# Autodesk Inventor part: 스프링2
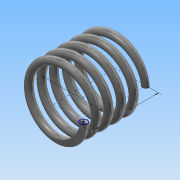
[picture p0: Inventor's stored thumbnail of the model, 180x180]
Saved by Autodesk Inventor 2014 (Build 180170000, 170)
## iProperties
Created: 2016-01
Part Number: 스프링2
Material: 강철, 탄소
Document SubType Name: Modeling
Designer: Administrator
Mass: 6.44239 g
Surface Area: 16.6857 cm^2
Volume: 0.818602 cm^3
Density: 7.87 g/cm^3
Appearance: 반연마
Author: Administrator
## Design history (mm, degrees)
sketch "스케치1"
  geometry: L1 (0, 0)-(8.5, 0); L2 (8.5, 0)-(8.5, 17.5); L3 (8.5, 17.5)-(0, 17.5); L4 (0, 17.5)-(0, 0); C1 r 1 at (8.5, 0)
  constraints: 8 end point, 2 parallel, 1 centre point, 1 coincident, 1 horizontal, 1 perpendicular
  dimensions: "d0" = 17.5 distance of L1.end L2.end (derived); "d1" = 2 diameter of C1; "d2" = 17 diameter of L2 L4
feature "코일1" sketch "스케치1" pitch "d3" = 10; turns "d5" = 5; dims "d4" = 17.5 (= d0), "d6" = 0, angle "d7" = 90 deg, angle "d8" = 90 deg, "d9" = 0, "d10" = 0
sketch "스케치2"
  geometry: L1 (-9.5, 0)-(-7.5, 0) reference; 1 further point
  constraints: 1 horizontal alignment
extrude "돌출1" cut sketch "스케치2" distance "d11" = 10; taper "d12" = 0 deg
node "작업 평면1"
sketch "스케치3"
  geometry: L1 (-7.5, 0)-(-9.5, 0) reference; 1 further point
  constraints: 1 horizontal alignment
extrude "돌출2" cut sketch "스케치3" stored distance "d14" = 10; taper "d15" = 0 deg
node "솔리드1"
node "절단 모서리 투영1"
node "절단 모서리 투영2"
other parameters: "d13" = 17.5 (= d0)
